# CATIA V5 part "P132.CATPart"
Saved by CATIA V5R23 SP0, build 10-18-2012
Part number: P132
Definition: Goupille elastique 6x30
Description: Goupille elastique ISO 8752 6x30
Bounding box of the stored display mesh (mm): x -25 to 0, y -2.952 to 2.989, z -2.997 to 2.997
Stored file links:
  C:\wamp\www\COURS\CONCEPTION GMP1\TITRE 02-SEMESTRE 2\03-TP7-PRESSE MECANIQUE\eleve\P132.CATPart
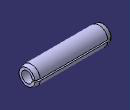
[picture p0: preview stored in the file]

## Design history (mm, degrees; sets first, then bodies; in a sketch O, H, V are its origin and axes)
Parameters
  Material = "St"
  d1_pin_nom_dia = 6 mm
  l_pin_length_nom = 25 mm
  d2_pin_id = 4 mm
  a_cham_max = 1.4 mm
  s_wall_th = 1.2 mm
  PartNumber = "Goupille elastique ISO 8752 6x30"
Body1 "PartBody" (main body)
  Sketch1 on zx-plane, origin (0, 0, 0), H (-1, 0, 0), V (0, 0, 1)
    point P1 (0, 2.6249)
    line L1 (0, 2.6249) -> (1.4, 3)
    point P2 (1.4, 3)
    point P3 (1.4, 3)
    line L2 (1.4, 3) -> (23.6, 3)
    point P4 (23.6, 3)
    line L3 (23.6, 3) -> (25, 2.6249)
    point P5 (25, 2.6249)
    point P6 (25, 2.6249)
    line L4 (25, 2.6249) -> (25, 1.8)
    line L5 (25, 1.8) -> (0, 1.8)
    line L6 (0, 1.8) -> (0, 2.6249)
    axis line L7 (-9.3888, 0) -> (37.524, 0)
    distance P1 L4 = 25 {= l_pin_length_nom}
    distance L5 L2 = 1.2 {= s_wall_th}
    angle L3 L2 = 15
    angle L1 L2 = 15
    distance L2 L7 = 3 {= d1_pin_nom_dia /2}
    distance V P2 = 1.4 {= a_cham_max}
    distance P4 P5 H = 1.4 {= a_cham_max}
    coincidence: P3 L1, P6 L3, P2 P3, P5 P6, P1 V
    horizontal: L2 H, L5 H, L7 H
    vertical: L4 V, L6 V
    fix: L7
  Shaft1: profile Sketch1, axis Sketch1.L7, angle 445, second angle -95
